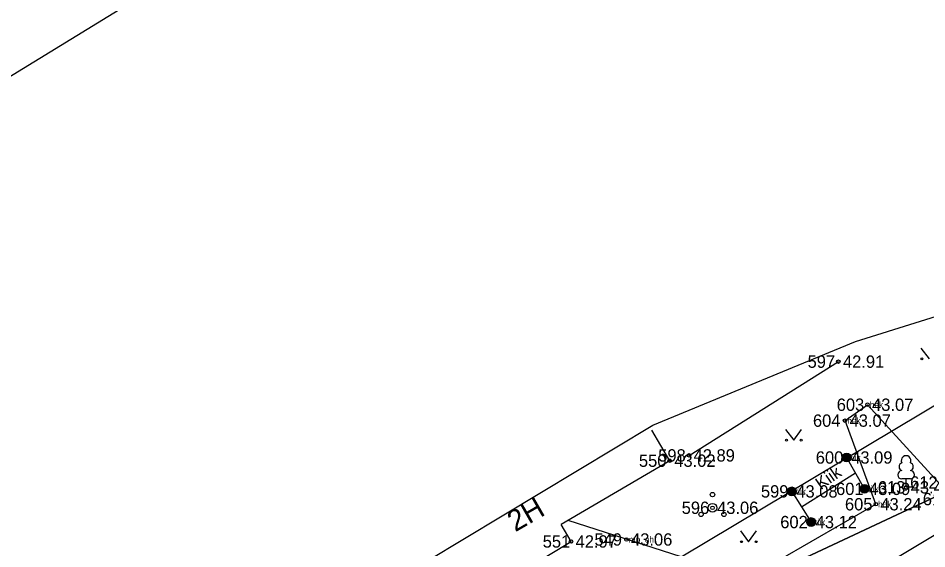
# Model space of a CAD drawing. Extents: x 505800 to 507326, y 6540058 to 6542128.
# Drawn here: x 506334.8 to 506386.4, y 6540354.7 to 6540384.8 of the extents above; entities that cross this region are included whole.
import ezdxf

# ---------------------------------------------------------------- set-up
doc = ezdxf.new("R2010")
doc.units = 0
for name, color, linetype in [('HALJASTUS', 7, 'Continuous'), ('HOONE', 7, 'Continuous'), ('KORGUS-EH2000', 7, 'Continuous'), ('MAAMUDEL', 7, 'Continuous'), ('MOOTKORG-EH2000', 7, 'Continuous'), ('MOOTMPUNKT', 7, 'Continuous'), ('MOOTNR', 7, 'Continuous'), ('MOOTPIIR', 7, 'Continuous'), ('MPOHULIIN', 7, 'Continuous'), ('PIIR', 7, 'Continuous'), ('POST', 7, 'Continuous'), ('PUU', 7, 'Continuous'), ('RAJATIS', 7, 'Continuous')]:
    doc.layers.add(name, color=color, linetype=linetype)

msp = doc.modelspace()

# ---------------------------------------------------------------- linework, layer by layer
at = {"layer": 'HALJASTUS'}
for p, q in [((506386.104, 6540366.077), (506386.568, 6540365.471)), ((506372.938, 6540359.994), (506381.42, 6540365.315)), ((506378.417, 6540361.47), (506378.88, 6540360.864)), ((506378.88, 6540360.864), (506379.326, 6540361.47)), ((506375.855, 6540355.702), (506376.318, 6540355.095)), ((506376.318, 6540355.095), (506376.764, 6540355.702))]:
    msp.add_line(p, q, dxfattribs=at)
msp.add_lwpolyline([(506383.074, 6540362.871), (506387.104, 6540358.456), (506388.363, 6540356.347), (506379.473, 6540351.019), (506371.247, 6540346.037), (506370.193, 6540346.236), (506368.863, 6540348.749), (506383.542, 6540357.221), (506381.795, 6540361.969), (506383.074, 6540362.871)], dxfattribs=at)
for centre in [(506386.166, 6540365.471), (506378.479, 6540360.864), (506379.308, 6540360.864), (506375.917, 6540355.095), (506376.746, 6540355.095)]:
    msp.add_circle(centre, 0.055, dxfattribs=at)
at = {"layer": 'HOONE'}
for p, q in [((506371.842, 6540359.694), (506370.828, 6540361.418)), ((506371.842, 6540359.694), (506365.676, 6540356.066)), ((506366.239, 6540355.108), (506365.676, 6540356.066)), ((506362.786, 6540353.037), (506366.239, 6540355.108))]:
    msp.add_line(p, q, dxfattribs=at)
at = {"layer": 'KORGUS-EH2000'}
for centre in [(506381.42, 6540365.315), (506383.074, 6540362.871), (506381.795, 6540361.969), (506372.938, 6540359.994), (506371.842, 6540359.694), (506381.887, 6540359.874), (506378.771, 6540357.95), (506382.898, 6540358.094), (506385.267, 6540358.181), (506374.271, 6540357.02), (506383.542, 6540357.221), (506379.869, 6540356.209), (506366.239, 6540355.108), (506369.387, 6540355.22)]:
    msp.add_circle(centre, 0.1, dxfattribs=at)
at = {"layer": 'MOOTMPUNKT'}
for centre in [(506381.42, 6540365.315), (506383.074, 6540362.871), (506381.795, 6540361.969), (506372.938, 6540359.994), (506371.842, 6540359.694), (506381.887, 6540359.874), (506378.771, 6540357.95), (506382.898, 6540358.094), (506385.267, 6540358.181), (506374.271, 6540357.02), (506383.542, 6540357.221), (506379.869, 6540356.209), (506366.239, 6540355.108), (506369.387, 6540355.22)]:
    msp.add_circle(centre, 0.1, dxfattribs=at)
at = {"layer": 'MOOTPIIR'}
msp.add_lwpolyline([(506240.253, 6540270.959), (506245.955, 6540263.864), (506266.133, 6540270.794), (506275.983, 6540276.683), (506285.511, 6540285.657), (506298.843, 6540299.878), (506301.086, 6540304.525), (506297.722, 6540312.738), (506305.023, 6540318.445), (506309.38, 6540311.746), (506312.325, 6540315.185), (506338.029, 6540330.648), (506336.908, 6540340.183), (506347.357, 6540347.554), (506370.89, 6540361.705), (506382.389, 6540366.462), (506390.076, 6540368.866), (506400.572, 6540374.13), (506410.565, 6540381.71), (506441.143, 6540393.151), (506453.59, 6540403.335), (506461.402, 6540393.473), (506495.448, 6540402.285)], dxfattribs=at)
at = {"layer": 'MPOHULIIN'}
msp.add_line((506372.493, 6540354.233), (506416.453, 6540380.536), dxfattribs=at)
msp.add_lwpolyline([(506338.064, 6540334.279), (506372.493, 6540354.233), (506366.077, 6540356.302)], dxfattribs=at)
at = {"layer": 'PIIR'}
msp.add_lwpolyline([(506326.14, 6540370.11), (506324.04, 6540375.18), (506354.05, 6540393.57), (506395.54, 6540418.74), (506427.6, 6540438.79), (506429.21, 6540436.36), (506458.7, 6540391.28), (506340.34, 6540335.82)], close=True, dxfattribs=at)
msp.add_lwpolyline([(506215.95, 6540254.34), (506268.55, 6540273.9), (506274.54, 6540277.85), (506304.35, 6540308.95), (506340.34, 6540335.82), (506458.7, 6540391.28), (506563.96, 6540420.02)], dxfattribs=at)
at = {"layer": 'POST'}
for centre, radius in [((506381.887, 6540359.874), 0.25), ((506381.887, 6540359.874), 0.225), ((506381.887, 6540359.874), 0.2), ((506381.887, 6540359.874), 0.175), ((506381.887, 6540359.874), 0.15), ((506381.887, 6540359.874), 0.125), ((506381.887, 6540359.874), 0.1), ((506381.887, 6540359.874), 0.075), ((506381.887, 6540359.874), 0.05), ((506381.887, 6540359.874), 0.025), ((506378.771, 6540357.95), 0.25), ((506378.771, 6540357.95), 0.225), ((506378.771, 6540357.95), 0.2), ((506378.771, 6540357.95), 0.175), ((506378.771, 6540357.95), 0.15), ((506378.771, 6540357.95), 0.125), ((506378.771, 6540357.95), 0.1), ((506378.771, 6540357.95), 0.075), ((506382.898, 6540358.094), 0.25), ((506382.898, 6540358.094), 0.225), ((506382.898, 6540358.094), 0.2), ((506382.898, 6540358.094), 0.175), ((506382.898, 6540358.094), 0.15), ((506382.898, 6540358.094), 0.125), ((506382.898, 6540358.094), 0.1), ((506382.898, 6540358.094), 0.075), ((506382.898, 6540358.094), 0.05), ((506382.898, 6540358.094), 0.025), ((506378.771, 6540357.95), 0.05), ((506378.771, 6540357.95), 0.025), ((506379.869, 6540356.209), 0.25), ((506379.869, 6540356.209), 0.225), ((506379.869, 6540356.209), 0.2), ((506379.869, 6540356.209), 0.175), ((506379.869, 6540356.209), 0.15), ((506379.869, 6540356.209), 0.125), ((506379.869, 6540356.209), 0.1), ((506379.869, 6540356.209), 0.075), ((506379.869, 6540356.209), 0.05), ((506379.869, 6540356.209), 0.025)]:
    msp.add_circle(centre, radius, dxfattribs=at)
at = {"layer": 'PUU'}
for p, q in [((506385.507, 6540358.656), (506385.027, 6540358.656)), ((506385.267, 6540358.181), (506385.267, 6540358.656)), ((506385.647, 6540358.181), (506385.267, 6540358.181))]:
    msp.add_line(p, q, dxfattribs=at)
for centre, radius in [((506374.271, 6540357.77), 0.125), ((506374.271, 6540357.02), 0.25), ((506373.621, 6540356.645), 0.125), ((506374.921, 6540356.645), 0.125)]:
    msp.add_circle(centre, radius, dxfattribs=at)
for centre, radius, start, end in [((506385.097, 6540359.354), 0.233, 109.0217, 253.1415), ((506385.267, 6540359.701), 0.277, 332.5799, 207.4201), ((506385.437, 6540359.354), 0.233, 286.8508, 70.9859), ((506385.029, 6540358.893), 0.238, 90.0016, 269.3953), ((506385.504, 6540358.893), 0.238, 270.6047, 89.9984)]:
    msp.add_arc(centre, radius, start, end, dxfattribs=at)
at = {"layer": 'RAJATIS'}
for p, q in [((506382.898, 6540358.094), (506381.887, 6540359.899)), ((506379.32, 6540357.079), (506382.392, 6540358.996)), ((506378.771, 6540357.95), (506379.869, 6540356.209))]:
    msp.add_line(p, q, dxfattribs=at)

# ---------------------------------------------------------------- texts
at = {"layer": 'HOONE'}
msp.add_text('2H', height=1.2, rotation=30.0352, dxfattribs=at).set_placement((506363.069, 6540355.623))
at = {"layer": 'KORGUS-EH2000'}
for s, p in [(' 42.91', (506381.42, 6540364.965)), (' 43.02', (506371.842, 6540359.344)), (' 43.24', (506383.542, 6540356.871)), (' 43.06', (506374.271, 6540356.67)), (' 42.97', (506366.239, 6540354.758))]:
    msp.add_text(s, height=0.7, dxfattribs=at).set_placement(p)
at = {"layer": 'MAAMUDEL'}
for s, p in [(' hek', (506383.074, 6540362.696)), (' hek', (506381.795, 6540361.794)), (' kiik', (506381.887, 6540359.699)), (' kiik', (506378.771, 6540357.775)), (' kiik', (506382.898, 6540357.919)), (' hek', (506383.542, 6540357.046)), (' kiik', (506379.869, 6540356.034)), (' mp_ohl', (506369.387, 6540355.045))]:
    msp.add_text(s, height=0.35, dxfattribs=at).set_placement(p)
at = {"layer": 'MOOTKORG-EH2000'}
for s, p in [(' 42.91', (506381.42, 6540364.965)), (' 43.07', (506383.074, 6540362.521)), (' 43.07', (506381.795, 6540361.619)), (' 42.89', (506372.938, 6540359.644)), (' 43.09', (506381.887, 6540359.524)), (' 43.02', (506371.842, 6540359.344)), (' 43.44', (506385.267, 6540357.831)), (' 43.08', (506378.771, 6540357.6)), (' 43.09', (506382.898, 6540357.744)), (' 43.24', (506383.542, 6540356.871)), (' 43.06', (506374.271, 6540356.67)), (' 43.12', (506379.869, 6540355.859)), (' 42.97', (506366.239, 6540354.758)), (' 43.06', (506369.387, 6540354.87))]:
    msp.add_text(s, height=0.7, dxfattribs=at).set_placement(p)
at = {"layer": 'MOOTNR'}
for s, p in [('597 ', (506379.67, 6540364.965)), ('603 ', (506381.325, 6540362.521)), ('604 ', (506379.975, 6540361.619)), ('598 ', (506371.188, 6540359.644)), ('600 ', (506380.137, 6540359.524)), ('550 ', (506370.092, 6540359.344)), ('613 ', (506383.657, 6540357.831)), ('612 ', (506385.494, 6540358.106)), ('599 ', (506377.021, 6540357.6)), ('601 ', (506381.288, 6540357.744)), ('605 ', (506381.792, 6540356.871)), ('618 ', (506386.212, 6540357.164)), ('596 ', (506372.521, 6540356.67)), ('602 ', (506378.119, 6540355.859)), ('551 ', (506364.629, 6540354.758)), ('549 ', (506367.567, 6540354.87))]:
    msp.add_text(s, height=0.7, dxfattribs=at).set_placement(p)
at = {"layer": 'RAJATIS'}
msp.add_text('Kiik', height=0.7, rotation=34.7195, dxfattribs=at).set_placement((506380.422, 6540358.015))

doc.saveas('drawing.dxf')
